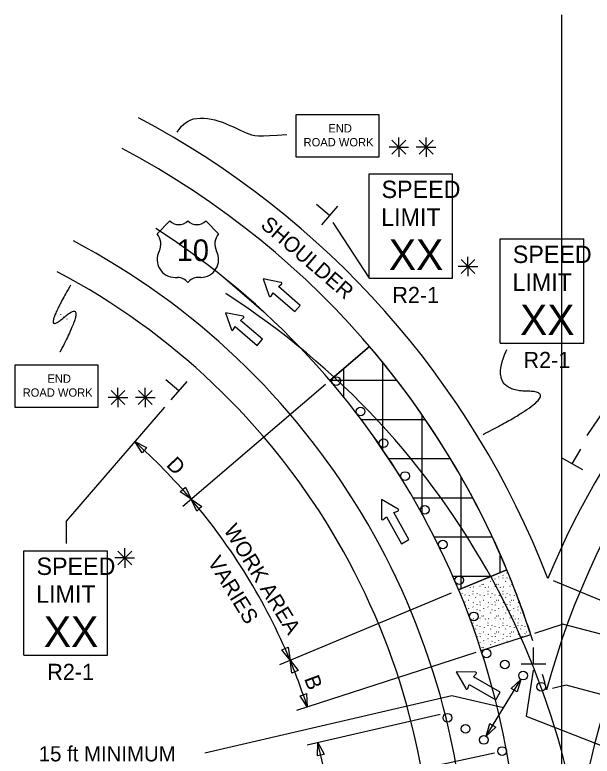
# Model space of a CAD drawing. Extents: x 16440 to 18464, y 5737 to 6974.
# Drawn here: x 16729.4 to 16994.8, y 6633.2 to 6974.1 of the extents above; entities that cross this region are included whole.
import ezdxf

# ---------------------------------------------------------------- set-up
doc = ezdxf.new("R2010")
doc.units = 0
for name, color, linetype in [('ALI_LEGAL_EX', 7, 'Continuous'), ('MT_SCRATCH_LEVEL_A', 7, 'Continuous'), ('MT_SCRATCH_LEVEL_E', 7, 'Continuous'), ('PAVT_EDGE_EX', 7, 'Continuous'), ('TRAFFIC_SIGNS_PR', 7, 'Continuous'), ('TYPICAL_EX', 7, 'Continuous'), ('TYPICAL_TEXT_DIMEN_PR', 7, 'Continuous')]:
    doc.layers.add(name, color=color, linetype=linetype)

msp = doc.modelspace()

# ---------------------------------------------------------------- linework, layer by layer
at = {"layer": 'ALI_LEGAL_EX'}
for p, q in [((16980.68, 6974.12), (16980.68, 6155.98)), ((16980.68, 6891.53), (16980.68, 6027.61))]:
    msp.add_line(p, q, dxfattribs=at)
for points in [[(16843.92, 6837.36), (16824.97, 6853.66)], [(16907.75, 6760.19), (16893.85, 6780.96)]]:
    msp.add_lwpolyline(points, dxfattribs=at)
for centre, radius, start, end in [((16597.51, 6569.52), 364, 0, 57.2958), ((16629.65, 6539.64), 364, 0, 57.2958), ((17325.51, 6555.03), 340, 129.5666, 180)]:
    msp.add_arc(centre, radius, start, end, dxfattribs=at)
at = {"layer": 'MT_SCRATCH_LEVEL_A'}
for p, q in [((16892.5, 6821.57), (16874.25, 6805.98)), ((16880.6, 6798.05), (16880.6, 6811.4)), ((16898.6, 6773.84), (16898.6, 6814.01)), ((16874.35, 6806.07), (16904.89, 6806.07)), ((16888.59, 6788.07), (16917.91, 6788.07)), ((16916.6, 6744.37), (16916.6, 6789.95)), ((16901.25, 6770.07), (16929.46, 6770.07)), ((16934.6, 6710.2), (16934.6, 6761.64)), ((16912.34, 6752.07), (16939.69, 6752.07)), ((16922.06, 6734.07), (16948.73, 6734.07)), ((16952.6, 6717.72), (16952.6, 6725.53)), ((16933.43, 6709.72), (16955.58, 6718.96)), ((16955.58, 6718.96), (16933.43, 6709.72)), ((16930.55, 6716.07), (16948.65, 6716.07)), ((16951.87, 6715.58), (16951.92, 6715.69)), ((16953.8, 6716.44), (16953.85, 6716.37)), ((16955.59, 6717.51), (16955.64, 6717.43)), ((16944.03, 6712.31), (16944.08, 6712.23)), ((16944.76, 6712.28), (16944.81, 6712.2)), ((16945.17, 6714.38), (16945.22, 6714.3)), ((16946.95, 6715.05), (16947, 6715.16)), ((16948.13, 6713.54), (16948.18, 6713.66)), ((16948.75, 6715.3), (16948.8, 6715.22)), ((16950.03, 6714.72), (16950.04, 6714.6)), ((16950.91, 6712.31), (16950.97, 6712.23)), ((16951.65, 6712.28), (16951.7, 6712.2)), ((16952.06, 6714.38), (16952.11, 6714.3)), ((16953.84, 6715.05), (16953.89, 6715.16)), ((16955.02, 6713.54), (16955.07, 6713.66)), ((16955.64, 6715.3), (16955.69, 6715.22)), ((16956.92, 6714.72), (16956.93, 6714.6)), ((16957.8, 6712.31), (16957.85, 6712.23)), ((16934.92, 6710.22), (16934.98, 6710.14)), ((16936.45, 6710.08), (16936.51, 6710)), ((16938.74, 6710.9), (16938.8, 6710.82)), ((16940.02, 6709.16), (16940.07, 6709.08)), ((16940.19, 6711.05), (16940.24, 6711.16)), ((16941.81, 6710.22), (16941.86, 6710.14)), ((16943.26, 6711.35), (16943.31, 6711.46)), ((16943.34, 6710.08), (16943.39, 6710)), ((16945.63, 6710.9), (16945.68, 6710.82)), ((16946.91, 6709.16), (16946.96, 6709.08)), ((16947.08, 6711.05), (16947.13, 6711.16)), ((16948.7, 6710.22), (16948.75, 6710.14)), ((16950.15, 6711.35), (16950.2, 6711.46)), ((16950.23, 6710.08), (16950.28, 6710)), ((16952.52, 6710.9), (16952.57, 6710.82)), ((16953.8, 6709.16), (16953.85, 6709.08)), ((16953.97, 6711.05), (16954.02, 6711.16)), ((16955.59, 6710.22), (16955.64, 6710.14)), ((16957.04, 6711.35), (16957.09, 6711.46)), ((16957.12, 6710.08), (16957.17, 6710)), ((16934.97, 6708.01), (16935.02, 6707.93)), ((16936.25, 6707.44), (16936.27, 6707.32)), ((16938.1, 6708.29), (16938.15, 6708.41)), ((16938.28, 6707.09), (16938.34, 6707.01)), ((16940.06, 6707.76), (16940.12, 6707.88)), ((16941.24, 6706.26), (16941.29, 6706.38)), ((16941.86, 6708.01), (16941.91, 6707.93)), ((16943.14, 6707.44), (16943.15, 6707.32)), ((16944.98, 6708.29), (16945.03, 6708.41)), ((16945.17, 6707.09), (16945.22, 6707.01)), ((16946.95, 6707.76), (16947, 6707.88)), ((16948.13, 6706.26), (16948.18, 6706.38)), ((16948.75, 6708.01), (16948.8, 6707.93)), ((16950.03, 6707.44), (16950.04, 6707.32)), ((16951.87, 6708.29), (16951.92, 6708.41)), ((16952.06, 6707.09), (16952.11, 6707.01)), ((16953.84, 6707.76), (16953.89, 6707.88)), ((16955.02, 6706.26), (16955.07, 6706.38)), ((16955.64, 6708.01), (16955.69, 6707.93)), ((16956.92, 6707.44), (16956.93, 6707.32)), ((16958.76, 6708.29), (16958.81, 6708.41)), ((16958.95, 6707.09), (16959, 6707.01)), ((16936.37, 6704.06), (16936.43, 6704.18)), ((16936.45, 6702.8), (16936.51, 6702.72)), ((16937.14, 6705.02), (16937.19, 6704.94)), ((16937.88, 6704.99), (16937.93, 6704.91)), ((16938.74, 6703.61), (16938.8, 6703.53)), ((16940.19, 6703.76), (16940.24, 6703.88)), ((16941.81, 6702.94), (16941.86, 6702.86)), ((16943.26, 6704.06), (16943.31, 6704.18)), ((16943.34, 6702.8), (16943.39, 6702.72)), ((16944.03, 6705.02), (16944.08, 6704.94)), ((16944.76, 6704.99), (16944.81, 6704.91)), ((16945.63, 6703.61), (16945.68, 6703.53)), ((16947.08, 6703.76), (16947.13, 6703.88)), ((16948.7, 6702.94), (16948.75, 6702.86)), ((16950.15, 6704.06), (16950.2, 6704.18)), ((16950.23, 6702.8), (16950.28, 6702.72)), ((16950.91, 6705.02), (16950.97, 6704.94)), ((16951.65, 6704.99), (16951.7, 6704.91)), ((16952.52, 6703.61), (16952.57, 6703.53)), ((16953.97, 6703.76), (16954.02, 6703.88)), ((16955.59, 6702.94), (16955.64, 6702.86)), ((16957.04, 6704.06), (16957.09, 6704.18)), ((16957.12, 6702.8), (16957.17, 6702.72)), ((16957.8, 6705.02), (16957.85, 6704.94)), ((16958.54, 6704.99), (16958.59, 6704.91)), ((16959.41, 6703.61), (16959.46, 6703.53)), ((16960.86, 6703.76), (16960.91, 6703.88)), ((16938.1, 6701.01), (16938.15, 6701.12)), ((16938.28, 6699.81), (16938.34, 6699.73)), ((16940.02, 6701.88), (16940.07, 6701.8)), ((16940.06, 6700.48), (16940.12, 6700.59)), ((16941.24, 6698.97), (16941.29, 6699.09)), ((16941.86, 6700.73), (16941.91, 6700.65)), ((16943.14, 6700.15), (16943.15, 6700.03)), ((16944.98, 6701.01), (16945.03, 6701.12)), ((16945.17, 6699.81), (16945.22, 6699.73)), ((16946.91, 6701.88), (16946.96, 6701.8)), ((16946.95, 6700.48), (16947, 6700.59)), ((16948.13, 6698.97), (16948.18, 6699.09)), ((16948.75, 6700.73), (16948.8, 6700.65)), ((16950.03, 6700.15), (16950.04, 6700.03)), ((16951.87, 6701.01), (16951.92, 6701.12)), ((16952.06, 6699.81), (16952.11, 6699.73)), ((16953.8, 6701.88), (16953.85, 6701.8)), ((16953.84, 6700.48), (16953.89, 6700.59)), ((16955.02, 6698.97), (16955.07, 6699.09)), ((16955.64, 6700.73), (16955.69, 6700.65)), ((16956.92, 6700.15), (16956.93, 6700.03)), ((16958.76, 6701.01), (16958.81, 6701.12)), ((16958.95, 6699.81), (16959, 6699.73)), ((16960.68, 6701.88), (16960.74, 6701.8)), ((16960.73, 6700.48), (16960.78, 6700.59)), ((16961.9, 6698.97), (16961.96, 6699.09)), ((16962.52, 6700.73), (16962.57, 6700.65)), ((16938.74, 6696.33), (16938.8, 6696.25)), ((16940.19, 6696.48), (16940.24, 6696.6)), ((16941.81, 6695.65), (16941.86, 6695.57)), ((16943.26, 6696.78), (16943.31, 6696.89)), ((16943.34, 6695.51), (16943.39, 6695.43)), ((16944.03, 6697.74), (16944.08, 6697.66)), ((16944.76, 6697.71), (16944.81, 6697.63)), ((16945.63, 6696.33), (16945.68, 6696.25)), ((16947.08, 6696.48), (16947.13, 6696.6)), ((16948.7, 6695.65), (16948.75, 6695.57)), ((16950.15, 6696.78), (16950.2, 6696.89)), ((16950.23, 6695.51), (16950.28, 6695.43)), ((16950.91, 6697.74), (16950.97, 6697.66)), ((16951.65, 6697.71), (16951.7, 6697.63)), ((16952.52, 6696.33), (16952.57, 6696.25)), ((16953.97, 6696.48), (16954.02, 6696.6)), ((16955.59, 6695.65), (16955.64, 6695.57)), ((16957.04, 6696.78), (16957.09, 6696.89)), ((16957.12, 6695.51), (16957.17, 6695.43)), ((16957.8, 6697.74), (16957.85, 6697.66)), ((16958.54, 6697.71), (16958.59, 6697.63)), ((16959.41, 6696.33), (16959.46, 6696.25)), ((16960.86, 6696.48), (16960.91, 6696.6)), ((16962.47, 6695.65), (16962.53, 6695.57)), ((16963.92, 6696.78), (16963.96, 6696.85)), ((16964, 6695.51), (16964.06, 6695.43)), ((16940.02, 6694.59), (16940.07, 6694.51)), ((16940.06, 6693.19), (16940.12, 6693.31)), ((16941.24, 6691.69), (16941.29, 6691.81)), ((16941.86, 6693.44), (16941.91, 6693.36)), ((16943.14, 6692.86), (16943.15, 6692.75)), ((16944.98, 6693.72), (16945.03, 6693.84)), ((16945.17, 6692.52), (16945.22, 6692.44)), ((16946.91, 6694.59), (16946.96, 6694.51)), ((16946.95, 6693.19), (16947, 6693.31)), ((16948.13, 6691.69), (16948.18, 6691.81)), ((16948.75, 6693.44), (16948.8, 6693.36)), ((16950.03, 6692.86), (16950.04, 6692.75)), ((16951.87, 6693.72), (16951.92, 6693.84)), ((16952.06, 6692.52), (16952.11, 6692.44)), ((16953.8, 6694.59), (16953.85, 6694.51)), ((16953.84, 6693.19), (16953.89, 6693.31)), ((16955.02, 6691.69), (16955.07, 6691.81)), ((16955.64, 6693.44), (16955.69, 6693.36)), ((16956.92, 6692.86), (16956.93, 6692.75)), ((16958.76, 6693.72), (16958.81, 6693.84)), ((16958.95, 6692.52), (16959, 6692.44)), ((16960.68, 6694.59), (16960.74, 6694.51)), ((16960.73, 6693.19), (16960.78, 6693.31)), ((16961.9, 6691.69), (16961.96, 6691.81)), ((16962.52, 6693.44), (16962.57, 6693.36)), ((16963.8, 6692.86), (16963.82, 6692.75)), ((16941.81, 6688.36), (16941.86, 6688.29)), ((16943.26, 6689.49), (16943.31, 6689.61)), ((16943.74, 6681.84), (16966.58, 6689.25)), ((16944.03, 6690.45), (16944.08, 6690.37)), ((16944.76, 6690.42), (16944.81, 6690.34)), ((16945.63, 6689.04), (16945.68, 6688.97)), ((16947.08, 6689.19), (16947.13, 6689.31)), ((16948.7, 6688.36), (16948.75, 6688.29)), ((16950.15, 6689.49), (16950.2, 6689.61)), ((16950.91, 6690.45), (16950.97, 6690.37)), ((16951.65, 6690.42), (16951.7, 6690.34)), ((16952.52, 6689.04), (16952.57, 6688.97)), ((16953.97, 6689.19), (16954.02, 6689.31)), ((16955.59, 6688.36), (16955.64, 6688.29)), ((16957.04, 6689.49), (16957.09, 6689.61)), ((16957.8, 6690.45), (16957.85, 6690.37)), ((16958.54, 6690.42), (16958.59, 6690.34)), ((16959.41, 6689.04), (16959.46, 6688.97)), ((16960.86, 6689.19), (16960.91, 6689.31)), ((16962.47, 6688.36), (16962.53, 6688.29)), ((16963.92, 6689.49), (16963.98, 6689.61)), ((16964.69, 6690.45), (16964.74, 6690.37)), ((16965.42, 6690.42), (16965.48, 6690.34)), ((16943.14, 6685.58), (16943.15, 6685.46)), ((16943.34, 6688.23), (16943.39, 6688.15)), ((16944.98, 6686.44), (16945.03, 6686.55)), ((16945.17, 6685.24), (16945.22, 6685.16)), ((16946.91, 6687.31), (16946.96, 6687.23)), ((16946.95, 6685.9), (16947, 6686.02)), ((16948.75, 6686.16), (16948.8, 6686.08)), ((16950.03, 6685.58), (16950.04, 6685.46)), ((16950.23, 6688.23), (16950.28, 6688.15)), ((16951.87, 6686.44), (16951.92, 6686.55)), ((16952.06, 6685.24), (16952.11, 6685.16)), ((16953.8, 6687.31), (16953.85, 6687.23)), ((16953.84, 6685.9), (16953.89, 6686.02)), ((16955.64, 6686.16), (16955.69, 6686.08)), ((16957.12, 6688.23), (16957.17, 6688.15)), ((16944.03, 6683.17), (16944.08, 6683.09)), ((16944.76, 6683.14), (16944.81, 6683.06)), ((16948.13, 6684.4), (16948.18, 6684.52))]:
    msp.add_line(p, q, dxfattribs=at)
for start, end in [(22.6538, 40.5126), (17.974, 22.6538)]:
    msp.add_arc((16597.51, 6569.52), 388, start, end, dxfattribs=at)
at = {"layer": 'MT_SCRATCH_LEVEL_E'}
for p, q in [((16851.73, 6851.09), (16843.54, 6852.67)), ((16843.54, 6852.67), (16846.35, 6844.83)), ((16850.54, 6849.14), (16851.94, 6850.28)), ((16860.59, 6840.5), (16850.54, 6849.14)), ((16847.18, 6844.75), (16848.1, 6846.31)), ((16848.1, 6846.31), (16858.15, 6837.66)), ((16858.15, 6837.66), (16860.59, 6840.5)), ((16834.35, 6835.57), (16826.16, 6837.15)), ((16826.16, 6837.15), (16828.97, 6829.31)), ((16833.16, 6833.62), (16834.56, 6834.76)), ((16843.21, 6824.97), (16833.16, 6833.62)), ((16829.8, 6829.23), (16830.72, 6830.78)), ((16830.72, 6830.78), (16840.77, 6822.14)), ((16840.77, 6822.14), (16843.21, 6824.97))]:
    msp.add_line(p, q, dxfattribs=at)
for centre, start, end in [((16851.63, 6850.64), 309.3361, 79.073), ((16846.78, 6845), 199.7248, 329.2637), ((16834.25, 6835.11), 309.3361, 79.073), ((16829.4, 6829.47), 199.7248, 329.2637)]:
    msp.add_arc(centre, 0.463, start, end, dxfattribs=at)
at = {"layer": 'PAVT_EDGE_EX'}
for centre, radius, start, end in [((16597.51, 6569.52), 404, 21.0961, 62.1564), ((16597.51, 6569.52), 388, 17.5132, 62.1564), ((17325.51, 6569.52), 380, 123.7854, 157.5011), ((16597.51, 6569.52), 340, 0, 62.1564), ((17325.51, 6569.52), 364, 123.7854, 165.0045), ((16597.51, 6569.52), 324, 0, 62.1564), ((16597.51, 6569.52), 388, 14.0482, 15.1223)]:
    msp.add_arc(centre, radius, start, end, dxfattribs=at)
at = {"layer": 'TRAFFIC_SIGNS_PR'}
for p, q in [((16892.23, 6901.02), (16930.63, 6901.02)), ((16892.23, 6853.02), (16892.23, 6901.02)), ((16930.63, 6853.02), (16930.63, 6901.02)), ((16952.57, 6871.13), (16990.97, 6871.13)), ((16952.57, 6823.13), (16952.57, 6871.13)), ((16990.97, 6823.13), (16990.97, 6871.13)), ((16892.23, 6853.02), (16930.63, 6853.02)), ((16952.57, 6823.13), (16990.97, 6823.13)), ((16733.58, 6727.69), (16771.97, 6727.69)), ((16733.58, 6679.69), (16733.58, 6727.69)), ((16771.97, 6679.69), (16771.97, 6727.69)), ((16733.58, 6679.69), (16771.97, 6679.69))]:
    msp.add_line(p, q, dxfattribs=at)
for points in [[(16858.53, 6908.89), (16896.93, 6908.89), (16896.93, 6928.09), (16858.53, 6928.09)], [(16729.36, 6793.78), (16767.76, 6793.78), (16767.76, 6812.98), (16729.36, 6812.98)]]:
    msp.add_lwpolyline(points, close=True, dxfattribs=at)
for centre in [(16877.1, 6805.72), (16888.37, 6791.69), (16898.94, 6777.12), (16908.78, 6762.05), (16917.89, 6746.49), (16926.19, 6730.56), (16933.71, 6714.2), (16940.41, 6697.5), (16946.29, 6680.49), (16954.68, 6675.38), (16963.06, 6670.27), (16971.44, 6665.16), (16928.27, 6650.92), (16936.65, 6645.81), (16945.03, 6640.7), (16953.42, 6635.59), (16953.42, 6635.59)]:
    msp.add_circle(centre, 2, dxfattribs=at)
at = {"layer": 'TYPICAL_EX'}
for p, q in [((16794.78, 6873.43), (16800.67, 6879.32)), ((16823.07, 6873.43), (16817.18, 6879.32)), ((16803.02, 6853.37), (16804.2, 6853.37)), ((16814.83, 6853.37), (16813.65, 6853.37))]:
    msp.add_line(p, q, dxfattribs=at)
for centre, radius, start, end in [((16804.8, 6883.62), 5.96, 226.1404, 313.8596), ((16813.05, 6883.62), 5.96, 226.1404, 313.8596), ((16789.19, 6868.71), 7.31, 333.0977, 40.1936), ((16828.66, 6868.71), 7.31, 139.8064, 206.9023), ((16803.03, 6861.61), 8.24, 152.6698, 269.9013), ((16814.81, 6861.61), 8.24, 270.0987, 27.3302), ((16804.21, 6847.46), 5.91, 37.1038, 90.1385), ((16813.63, 6847.46), 5.91, 89.8615, 142.8962)]:
    msp.add_arc(centre, radius, start, end, dxfattribs=at)
at = {"layer": 'TYPICAL_TEXT_DIMEN_PR'}
for p, q in [((16905.96, 6913.26), (16905.96, 6917.72)), ((16918.51, 6913.26), (16918.51, 6917.72)), ((16905.96, 6913.26), (16901.42, 6913.26)), ((16902.77, 6916.45), (16909.14, 6910.07)), ((16909.14, 6916.45), (16902.77, 6910.07)), ((16905.96, 6913.26), (16909.14, 6913.26)), ((16905.96, 6913.26), (16910.43, 6913.26)), ((16905.96, 6913.26), (16905.96, 6908.76)), ((16918.51, 6913.26), (16913.98, 6913.26)), ((16921.7, 6916.45), (16915.32, 6910.07)), ((16915.33, 6916.45), (16921.7, 6910.07)), ((16918.51, 6913.26), (16921.7, 6913.26)), ((16918.51, 6913.26), (16922.99, 6913.26)), ((16918.51, 6913.26), (16918.51, 6908.76)), ((16874.03, 6881.81), (16868.13, 6886.89)), ((16877.7, 6886.08), (16870.36, 6877.55)), ((16875.65, 6878.64), (16892.23, 6853.02)), ((16937.72, 6858.44), (16937.72, 6862.9)), ((16934.54, 6861.63), (16940.91, 6855.25)), ((16940.91, 6861.63), (16934.54, 6855.25)), ((16937.72, 6858.44), (16933.19, 6858.44)), ((16937.72, 6858.44), (16940.91, 6858.44)), ((16937.72, 6858.44), (16942.2, 6858.44)), ((16937.72, 6858.44), (16937.72, 6853.94)), ((16755, 6849.79), (16755, 6849.79)), ((16755, 6849.79), (16755, 6849.79)), ((16753.21, 6846.62), (16753.21, 6846.62)), ((16753.21, 6846.62), (16753.21, 6846.62)), ((16754.09, 6848.22), (16754.09, 6848.22)), ((16754.09, 6848.22), (16754.09, 6848.22)), ((16750.89, 6841.69), (16750.89, 6841.69)), ((16750.89, 6841.69), (16750.89, 6841.69)), ((16751.59, 6843.37), (16751.59, 6843.36)), ((16751.59, 6843.37), (16751.59, 6843.36)), ((16752.37, 6845.01), (16752.37, 6845.01)), ((16752.37, 6845.01), (16752.37, 6845.01)), ((16750.33, 6839.95), (16750.33, 6839.95)), ((16750.33, 6839.95), (16750.33, 6839.95)), ((16750.05, 6838.15), (16750.07, 6838.15)), ((16750.05, 6838.15), (16750.07, 6838.15)), ((16750.48, 6836.39), (16750.51, 6836.41)), ((16750.48, 6836.39), (16750.51, 6836.41)), ((16751.83, 6835.17), (16751.84, 6835.18)), ((16751.83, 6835.17), (16751.84, 6835.18)), ((16753.36, 6834.17), (16753.34, 6834.15)), ((16753.36, 6834.17), (16753.34, 6834.15)), ((16754.39, 6832.67), (16754.36, 6832.66)), ((16754.39, 6832.67), (16754.36, 6832.66)), ((16992.47, 6780.68), (17029.33, 6834.75)), ((16754.31, 6829.06), (16754.3, 6829.06)), ((16754.31, 6829.06), (16754.3, 6829.06)), ((16754.58, 6830.86), (16754.57, 6830.86)), ((16754.58, 6830.86), (16754.57, 6830.86)), ((16753.19, 6825.6), (16753.19, 6825.6)), ((16753.19, 6825.6), (16753.19, 6825.6)), ((16753.81, 6827.31), (16753.81, 6827.31)), ((16753.81, 6827.31), (16753.81, 6827.31)), ((16751.73, 6822.26), (16751.73, 6822.27)), ((16751.73, 6822.26), (16751.73, 6822.27)), ((16752.49, 6823.92), (16752.49, 6823.92)), ((16752.49, 6823.92), (16752.49, 6823.92)), ((16874.25, 6805.98), (16892.49, 6821.57)), ((16750.1, 6819.01), (16750.1, 6819.01)), ((16750.1, 6819.01), (16750.1, 6819.01)), ((16750.93, 6820.63), (16750.93, 6820.63)), ((16750.93, 6820.63), (16750.93, 6820.63)), ((16804.71, 6801.27), (16798.81, 6806.35)), ((16808.38, 6805.53), (16801.05, 6797.01)), ((16806.58, 6748.16), (16872.22, 6804.24)), ((16773.6, 6801.34), (16779.97, 6794.97)), ((16779.97, 6801.34), (16773.6, 6794.97)), ((16776.79, 6798.15), (16776.79, 6802.61)), ((16792.53, 6801.34), (16786.15, 6794.97)), ((16786.16, 6801.34), (16792.53, 6794.97)), ((16789.34, 6798.15), (16789.34, 6802.61)), ((16776.79, 6798.15), (16772.25, 6798.15)), ((16776.79, 6798.15), (16779.97, 6798.15)), ((16776.79, 6798.15), (16781.26, 6798.15)), ((16776.79, 6798.15), (16776.79, 6793.65)), ((16789.34, 6798.15), (16784.81, 6798.15)), ((16789.34, 6798.15), (16792.53, 6798.15)), ((16789.34, 6798.15), (16793.82, 6798.15)), ((16789.34, 6798.15), (16789.34, 6793.65)), ((16753.06, 6741.26), (16798.27, 6793.78)), ((16787.88, 6772.78), (16784.57, 6777.86)), ((16784.57, 6777.86), (16789.98, 6775.12)), ((16788.93, 6773.95), (16787.88, 6772.78)), ((16789.98, 6775.12), (16788.93, 6773.95)), ((16985.67, 6767.67), (16989.56, 6774.42)), ((16990.54, 6764.86), (16980.8, 6770.49)), ((16806.58, 6755.86), (16807.77, 6756.88)), ((16807.77, 6756.88), (16810.38, 6751.41)), ((16805.38, 6754.84), (16806.58, 6755.86)), ((16810.38, 6751.41), (16805.38, 6754.84)), ((16813, 6745.93), (16810.38, 6751.41)), ((16810.38, 6751.41), (16815.39, 6747.97)), ((16897.96, 6751.32), (16897.9, 6742.44)), ((16905.59, 6746.74), (16897.96, 6751.32)), ((16814.19, 6746.95), (16813, 6745.93)), ((16815.39, 6747.97), (16814.19, 6746.95)), ((16898.71, 6742.05), (16900.2, 6743.27)), ((16900.2, 6743.27), (16907.11, 6730.93)), ((16903.68, 6745.22), (16905.5, 6745.85)), ((16910.59, 6732.88), (16903.68, 6745.22)), ((16753.06, 6731.04), (16753.06, 6741.26)), ((16907.11, 6730.93), (16910.59, 6732.88)), ((16776.76, 6727.57), (16783.14, 6721.2)), ((16783.14, 6727.57), (16776.76, 6721.2)), ((16779.95, 6724.39), (16779.95, 6728.84)), ((16779.95, 6724.39), (16775.42, 6724.39)), ((16779.95, 6724.39), (16783.14, 6724.39)), ((16779.95, 6724.39), (16784.43, 6724.39)), ((16779.95, 6724.39), (16779.95, 6719.89)), ((16933.43, 6709.71), (16955.58, 6718.96)), ((17093.61, 6665.56), (16977.03, 6713.85)), ((16851.29, 6675.44), (16930.17, 6708.36)), ((16968.4, 6689.84), (16981.21, 6693.99)), ((17093.19, 6664), (16981.21, 6693.99)), ((16852.2, 6682.17), (16853.65, 6682.77)), ((16855.91, 6677.36), (16852.2, 6682.17)), ((16853.65, 6682.77), (16855.1, 6683.38)), ((16855.1, 6683.38), (16855.91, 6677.36)), ((16967.87, 6675.48), (16967.87, 6683.27)), ((16859.09, 6654.38), (16941.54, 6681.12)), ((16856.72, 6671.35), (16855.91, 6677.36)), ((16855.91, 6677.36), (16859.62, 6672.56)), ((16973.49, 6675.48), (16962.24, 6675.48)), ((16858.17, 6671.95), (16856.72, 6671.35)), ((16859.62, 6672.56), (16858.17, 6671.95)), ((16941.15, 6671.92), (16932.25, 6671.94)), ((16932.25, 6671.94), (16936.76, 6664.29)), ((16967.78, 6672.77), (16964.45, 6651.69)), ((16940.29, 6669.64), (16941.52, 6671.12)), ((16952.55, 6662.6), (16940.29, 6669.64)), ((16946.08, 6642.4), (16962.02, 6668.56)), ((16957.63, 6664.37), (16962.02, 6668.56)), ((16962.02, 6668.56), (16960.31, 6662.74)), ((16963.06, 6670.27), (16963.06, 6670.27)), ((16937.65, 6664.37), (16938.3, 6666.18)), ((16938.3, 6666.18), (16950.56, 6659.13)), ((16969.74, 6666.21), (16969.74, 6666.2)), ((16982.82, 6665.93), (16976.66, 6664.39)), ((17086.29, 6638.21), (16982.82, 6665.93)), ((16860.54, 6661.01), (16862.04, 6661.49)), ((16863.85, 6655.92), (16860.54, 6661.01)), ((16862.04, 6661.49), (16863.53, 6661.98)), ((16863.53, 6661.98), (16863.85, 6655.92)), ((16950.56, 6659.13), (16952.55, 6662.6)), ((16958.97, 6663.56), (16957.63, 6664.37)), ((16960.31, 6662.74), (16958.97, 6663.56)), ((16930.24, 6660.9), (16816.71, 6634.55)), ((16954.05, 6655.48), (16930.24, 6660.9)), ((16924.96, 6652.39), (16863.76, 6638.33)), ((16964.45, 6651.69), (17046.11, 6619.48)), ((16946.08, 6642.4), (16947.78, 6648.23)), ((16947.78, 6648.23), (16949.13, 6647.41)), ((16949.13, 6647.41), (16950.47, 6646.59)), ((16950.47, 6646.59), (16946.08, 6642.4)), ((16868.58, 6633.38), (16868.64, 6639.45)), ((16868.64, 6639.45), (16871.62, 6634.16)), ((16840.84, 6611.45), (16949.94, 6634.73)), ((16870.1, 6633.77), (16868.58, 6633.38)), ((16871.62, 6634.16), (16870.1, 6633.77))]:
    msp.add_line(p, q, dxfattribs=at)
for centre, radius, start, end in [((16597.51, 6569.52), 280, 40.5126, 48.082), ((16597.51, 6569.52), 280, 22.6539, 40.5126), ((16905.32, 6746.32), 0.494, 289.2925, 59.0295), ((16898.4, 6742.44), 0.494, 179.6812, 309.2202), ((16597.51, 6569.52), 280, 17.974, 22.6539), ((16941.14, 6671.42), 0.494, 320.1573, 89.8942), ((16937.18, 6664.54), 0.494, 210.5459, 340.0849), ((16597.51, 6569.52), 280, 10.0461, 14.4629)]:
    msp.add_arc(centre, radius, start, end, dxfattribs=at)
for points, degree in [([(16803.94, 6920.13), (16804.68, 6921.24), (16808.91, 6927.57), (16823.23, 6926.36), (16836.9, 6918.75), (16841.37, 6918.06), (16854.42, 6919.1)], 3), ([(16755, 6849.79), (16740.54, 6825.17), (16763.75, 6845.02), (16750.1, 6819.01)], 2), ([(16944.67, 6781.19), (16983.59, 6801.04), (16946.72, 6801.04), (16955.6, 6820.2)], 2)]:
    msp.add_open_spline(points, degree=degree, dxfattribs=at)

# ---------------------------------------------------------------- texts
at = {"layer": 'TRAFFIC_SIGNS_PR'}
for s, height, p in [('END', 3.831, (16873.53, 6920.02)), ('ROAD WORK', 3.831, (16862.14, 6913.63)), ('SPEED', 8, (16898, 6889.88)), ('LIMIT', 8, (16897.84, 6877.08)), ('XX', 14.031, (16901.34, 6856.78)), ('SPEED', 8, (16958.34, 6859.99)), ('LIMIT', 8, (16958.18, 6847.19)), ('R2-1', 7.44, (16902.91, 6841.58)), ('XX', 14.031, (16961.69, 6826.89)), ('R2-1', 7.44, (16963.25, 6811.69)), ('END', 3.831, (16744.36, 6804.91)), ('ROAD WORK', 3.831, (16732.97, 6798.52)), ('SPEED', 8, (16739.34, 6716.56)), ('LIMIT', 8, (16739.18, 6703.76)), ('XX', 14.031, (16742.69, 6683.45)), ('R2-1', 7.44, (16744.25, 6668.26))]:
    msp.add_text(s, height=height, dxfattribs=at).set_placement(p)
at = {"layer": 'TYPICAL_EX'}
msp.add_text('10', height=10, dxfattribs=at).set_placement((16803.77, 6860.85))
at = {"layer": 'TYPICAL_TEXT_DIMEN_PR'}
for s, rotation, p in [('SHOULDER', 319.2839, (16841.92, 6876.78)), ('D', 314.2974, (16798.64, 6766.81)), ('WORK AREA', 301.5829, (16825.2, 6737.26)), ('VARIES', 301.5829, (16817.8, 6722.56)), ('B', 290.315, (16862.32, 6668.9))]:
    msp.add_text(s, height=7, rotation=rotation, dxfattribs=at).set_placement(p)
msp.add_text('15 ft MINIMUM', height=7, dxfattribs=at).set_placement((16740.39, 6630.83))

doc.saveas('drawing.dxf')
